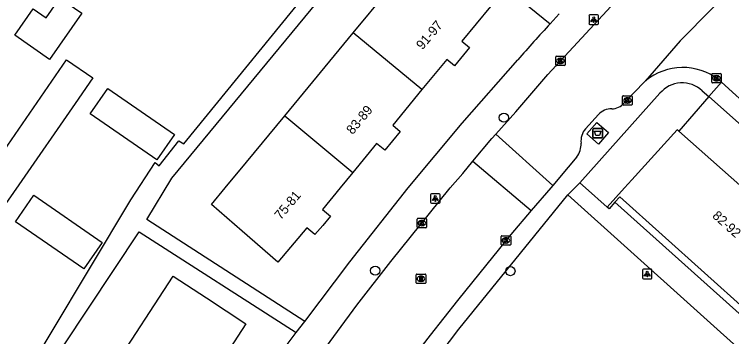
# Model space of a CAD drawing. Extents: x 160026 to 161302, y 384757 to 385701.
# Drawn here: x 160200.9 to 160276.8, y 385484.3 to 385518.4 of the extents above; entities that cross this region are included whole.
import ezdxf

# ---------------------------------------------------------------- set-up
doc = ezdxf.new("R2010")
doc.units = 0
for name, color, linetype in [('IMGEO_Afval_apart_plaats', 7, 'Continuous'), ('IMGEO_Boom', 7, 'Continuous'), ('IMGEO_Kolk', 7, 'Continuous'), ('IMGEO_Lichtpunt', 7, 'Continuous'), ('IMGEO_Pand', 7, 'Continuous'), ('IMGEO_Pand_nummerreeks', 7, 'Continuous'), ('IMGEO_Rijbaan_lokaal_gesloten', 7, 'Continuous'), ('IMGEO_Rijbaan_lokaal_open', 7, 'Continuous'), ('IMGEO_Rioolput', 7, 'Continuous'), ('IMGEO_Voetpad_gesloten', 7, 'Continuous'), ('IMGEO_Voetpad_open', 7, 'Continuous')]:
    doc.layers.add(name, color=color, linetype=linetype)

msp = doc.modelspace()

# ---------------------------------------------------------------- linework, layer by layer
at = {"layer": 'IMGEO_Afval_apart_plaats'}
for p, q in [((160262.147, 385505.395), (160262.147, 385506.195)), ((160262.147, 385506.195), (160262.147, 385505.395)), ((160262.247, 385506.295), (160263.037, 385506.295)), ((160263.037, 385506.295), (160262.247, 385506.295)), ((160263.137, 385506.195), (160263.137, 385505.395)), ((160263.137, 385505.395), (160263.137, 385506.195)), ((160263.037, 385505.295), (160262.247, 385505.295)), ((160262.247, 385505.295), (160263.037, 385505.295))]:
    msp.add_line(p, q, dxfattribs=at)
msp.add_lwpolyline([(160262.29, 385506.009), (160262.994, 385506.009), (160262.845, 385505.539), (160262.439, 385505.539), (160262.29, 385506.009)], dxfattribs=at)
for centre, start, end in [((160262.247, 385506.195), 90, 180), ((160262.247, 385506.195), 90, 180), ((160263.037, 385506.195), 0, 90), ((160263.037, 385506.195), 360, 90), ((160262.247, 385505.395), 180, 270), ((160262.247, 385505.395), 180, 270), ((160263.037, 385505.395), 270, 0), ((160263.037, 385505.395), 270, 0)]:
    msp.add_arc(centre, 0.1, start, end, dxfattribs=at)
at = {"layer": 'IMGEO_Boom'}
for centre in [(160252.715, 385507.448), (160239.098, 385491.254), (160253.404, 385491.208)]:
    msp.add_circle(centre, 0.489, dxfattribs=at)
at = {"layer": 'IMGEO_Kolk'}
for p, q in [((160258.2, 385513.021), (160258.2, 385513.873)), ((160258.275, 385513.947), (160259.127, 385513.947)), ((160258.688, 385513.727), (160258.713, 385513.727)), ((160259.201, 385513.873), (160259.201, 385513.021)), ((160259.127, 385512.947), (160258.275, 385512.947)), ((160258.711, 385513.167), (160258.686, 385513.167)), ((160274.798, 385512.117), (160275.65, 385512.117)), ((160274.723, 385511.191), (160274.723, 385512.043)), ((160275.234, 385511.337), (160275.209, 385511.337)), ((160275.211, 385511.897), (160275.236, 385511.897)), ((160275.724, 385512.043), (160275.724, 385511.191)), ((160275.65, 385511.117), (160274.798, 385511.117)), ((160265.285, 385508.841), (160265.285, 385509.693)), ((160265.36, 385509.767), (160266.212, 385509.767)), ((160265.773, 385509.547), (160265.798, 385509.547)), ((160266.286, 385509.693), (160266.286, 385508.841)), ((160266.212, 385508.767), (160265.36, 385508.767)), ((160265.796, 385508.987), (160265.771, 385508.987)), ((160243.536, 385495.866), (160243.536, 385496.718)), ((160243.611, 385496.792), (160244.463, 385496.792)), ((160244.024, 385496.572), (160244.049, 385496.572)), ((160244.537, 385496.718), (160244.537, 385495.866)), ((160244.463, 385495.792), (160243.611, 385495.792)), ((160244.047, 385496.012), (160244.022, 385496.012)), ((160252.434, 385494.024), (160252.434, 385494.876)), ((160252.509, 385494.95), (160253.361, 385494.95)), ((160252.922, 385494.73), (160252.947, 385494.73)), ((160253.435, 385494.876), (160253.435, 385494.024)), ((160253.361, 385493.95), (160252.509, 385493.95)), ((160252.945, 385494.17), (160252.92, 385494.17))]:
    msp.add_line(p, q, dxfattribs=at)
for points in [[(160258.2, 385513.021), (160258.2, 385513.873)], [(160258.275, 385513.947), (160259.127, 385513.947)], [(160258.521, 385513.647), (160258.644, 385513.647), (160258.644, 385513.496), (160258.774, 385513.647), (160258.938, 385513.647), (160258.792, 385513.496), (160258.945, 385513.247), (160258.793, 385513.247), (160258.708, 385513.411), (160258.644, 385513.344), (160258.644, 385513.247), (160258.521, 385513.247), (160258.521, 385513.647)], [(160259.201, 385513.873), (160259.201, 385513.021)], [(160259.127, 385512.947), (160258.275, 385512.947)], [(160274.798, 385512.117), (160275.65, 385512.117)], [(160274.723, 385511.191), (160274.723, 385512.043)], [(160275.044, 385511.817), (160275.167, 385511.817), (160275.167, 385511.666), (160275.297, 385511.817), (160275.461, 385511.817), (160275.315, 385511.666), (160275.468, 385511.417), (160275.316, 385511.417), (160275.231, 385511.581), (160275.167, 385511.514), (160275.167, 385511.417), (160275.044, 385511.417), (160275.044, 385511.817)], [(160275.724, 385512.043), (160275.724, 385511.191)], [(160275.65, 385511.117), (160274.798, 385511.117)], [(160265.285, 385508.841), (160265.285, 385509.693)], [(160265.36, 385509.767), (160266.212, 385509.767)], [(160265.606, 385509.467), (160265.729, 385509.467), (160265.729, 385509.316), (160265.859, 385509.467), (160266.023, 385509.467), (160265.877, 385509.316), (160266.03, 385509.067), (160265.878, 385509.067), (160265.793, 385509.231), (160265.729, 385509.164), (160265.729, 385509.067), (160265.606, 385509.067), (160265.606, 385509.467)], [(160266.286, 385509.693), (160266.286, 385508.841)], [(160266.212, 385508.767), (160265.36, 385508.767)], [(160243.536, 385495.866), (160243.536, 385496.718)], [(160243.611, 385496.792), (160244.463, 385496.792)], [(160243.857, 385496.492), (160243.98, 385496.492), (160243.98, 385496.341), (160244.11, 385496.492), (160244.274, 385496.492), (160244.128, 385496.341), (160244.281, 385496.092), (160244.129, 385496.092), (160244.044, 385496.256), (160243.98, 385496.189), (160243.98, 385496.092), (160243.857, 385496.092), (160243.857, 385496.492)], [(160244.537, 385496.718), (160244.537, 385495.866)], [(160244.463, 385495.792), (160243.611, 385495.792)], [(160252.434, 385494.024), (160252.434, 385494.876)], [(160252.509, 385494.95), (160253.361, 385494.95)], [(160252.755, 385494.65), (160252.878, 385494.65), (160252.878, 385494.499), (160253.008, 385494.65), (160253.172, 385494.65), (160253.026, 385494.499), (160253.179, 385494.25), (160253.027, 385494.25), (160252.942, 385494.414), (160252.878, 385494.347), (160252.878, 385494.25), (160252.755, 385494.25), (160252.755, 385494.65)], [(160253.435, 385494.876), (160253.435, 385494.024)], [(160253.361, 385493.95), (160252.509, 385493.95)]]:
    msp.add_lwpolyline(points, dxfattribs=at)
for centre, start, end in [((160258.277, 385513.871), 91.55205, 178.44795), ((160258.277, 385513.871), 91.55205, 178.44795), ((160259.125, 385513.871), 1.55205, 88.44795), ((160259.125, 385513.871), 1.55205, 88.44795), ((160258.277, 385513.023), 181.55205, 268.44795), ((160258.277, 385513.023), 181.55205, 268.44795), ((160259.125, 385513.023), 271.55205, 358.44795), ((160259.125, 385513.023), 271.55205, 358.44795), ((160274.8, 385512.041), 91.55205, 178.44795), ((160274.8, 385512.041), 91.55205, 178.44795), ((160275.648, 385512.041), 1.55205, 88.44795), ((160275.648, 385512.041), 1.55205, 88.44795), ((160274.8, 385511.193), 181.55205, 268.44795), ((160274.8, 385511.193), 181.55205, 268.44795), ((160275.648, 385511.193), 271.55205, 358.44795), ((160275.648, 385511.193), 271.55205, 358.44795), ((160265.362, 385509.691), 91.55205, 178.44795), ((160265.362, 385509.691), 91.55205, 178.44795), ((160266.21, 385509.691), 1.55205, 88.44795), ((160266.21, 385509.691), 1.55205, 88.44795), ((160265.362, 385508.843), 181.55205, 268.44795), ((160265.362, 385508.843), 181.55205, 268.44795), ((160266.21, 385508.843), 271.55205, 358.44795), ((160266.21, 385508.843), 271.55205, 358.44795), ((160243.613, 385496.716), 91.55205, 178.44795), ((160243.613, 385496.716), 91.55205, 178.44795), ((160244.461, 385496.716), 1.55205, 88.44795), ((160244.461, 385496.716), 1.55205, 88.44795), ((160243.613, 385495.868), 181.55205, 268.44795), ((160243.613, 385495.868), 181.55205, 268.44795), ((160244.461, 385495.868), 271.55205, 358.44795), ((160244.461, 385495.868), 271.55205, 358.44795), ((160252.511, 385494.874), 91.55205, 178.44795), ((160252.511, 385494.874), 91.55205, 178.44795), ((160253.359, 385494.874), 1.55205, 88.44795), ((160253.359, 385494.874), 1.55205, 88.44795), ((160252.511, 385494.026), 181.55205, 268.44795), ((160252.511, 385494.026), 181.55205, 268.44795), ((160253.359, 385494.026), 271.55205, 358.44795), ((160253.359, 385494.026), 271.55205, 358.44795)]:
    msp.add_arc(centre, 0.0765, start, end, dxfattribs=at)
for centre, major_axis, ratio, start_param, end_param in [((160258.687, 385513.447), (-0.387, 0.002), 0.722429, 4.712389, 7.853982), ((160258.712, 385513.447), (-0.39, 0.002), 0.717154, 1.570796, 4.712389), ((160275.21, 385511.617), (-0.387, 0.002), 0.722429, 4.712389, 7.853982), ((160275.235, 385511.617), (-0.39, 0.002), 0.717154, 1.570796, 4.712389), ((160265.772, 385509.267), (-0.387, 0.002), 0.722429, 4.712389, 7.853982), ((160265.797, 385509.267), (-0.39, 0.002), 0.717154, 1.570796, 4.712389), ((160244.023, 385496.292), (-0.387, 0.002), 0.722429, 4.712389, 7.853982), ((160244.048, 385496.292), (-0.39, 0.002), 0.717154, 1.570796, 4.712389), ((160252.921, 385494.45), (-0.387, 0.002), 0.722429, 4.712389, 7.853982), ((160252.946, 385494.45), (-0.39, 0.002), 0.717154, 1.570796, 4.712389)]:
    msp.add_ellipse(centre, major_axis=major_axis, ratio=ratio, start_param=start_param, end_param=end_param, dxfattribs=at)
at = {"layer": 'IMGEO_Lichtpunt'}
for p, q in [((160261.726, 385518.221), (160261.726, 385517.414)), ((160261.726, 385518.221), (160261.726, 385517.414)), ((160262.628, 385518.316), (160261.82, 385518.316)), ((160262.628, 385518.316), (160261.82, 385518.316)), ((160262.722, 385517.414), (160262.722, 385518.221)), ((160262.722, 385517.414), (160262.722, 385518.221)), ((160261.82, 385517.32), (160262.628, 385517.32)), ((160261.82, 385517.32), (160262.628, 385517.32)), ((160244.959, 385499.293), (160244.959, 385498.486)), ((160244.959, 385499.293), (160244.959, 385498.486)), ((160245.861, 385499.388), (160245.053, 385499.388)), ((160245.861, 385499.388), (160245.053, 385499.388)), ((160245.955, 385498.486), (160245.955, 385499.293)), ((160245.955, 385498.486), (160245.955, 385499.293)), ((160245.053, 385498.392), (160245.861, 385498.392)), ((160245.053, 385498.392), (160245.861, 385498.392)), ((160267.393, 385491.302), (160267.393, 385490.495)), ((160267.393, 385491.302), (160267.393, 385490.495)), ((160268.295, 385491.397), (160267.487, 385491.397)), ((160268.295, 385491.397), (160267.487, 385491.397)), ((160268.389, 385490.495), (160268.389, 385491.302)), ((160268.389, 385490.495), (160268.389, 385491.302)), ((160267.487, 385490.401), (160268.295, 385490.401)), ((160267.487, 385490.401), (160268.295, 385490.401))]:
    msp.add_line(p, q, dxfattribs=at)
for points in [[(160262.1, 385517.885), (160262.139, 385517.857), (160261.951, 385517.595), (160261.913, 385517.622), (160262.1, 385517.885)], [(160262.202, 385517.837), (160262.249, 385517.837), (160262.249, 385517.515), (160262.202, 385517.515), (160262.202, 385517.837)], [(160262.312, 385517.857), (160262.35, 385517.884), (160262.537, 385517.622), (160262.498, 385517.594), (160262.312, 385517.857)], [(160245.333, 385498.957), (160245.372, 385498.929), (160245.184, 385498.667), (160245.146, 385498.694), (160245.333, 385498.957)], [(160245.435, 385498.909), (160245.482, 385498.909), (160245.482, 385498.587), (160245.435, 385498.587), (160245.435, 385498.909)], [(160245.545, 385498.929), (160245.583, 385498.956), (160245.77, 385498.694), (160245.731, 385498.666), (160245.545, 385498.929)], [(160267.767, 385490.966), (160267.806, 385490.938), (160267.618, 385490.676), (160267.58, 385490.703), (160267.767, 385490.966)], [(160267.869, 385490.918), (160267.916, 385490.918), (160267.916, 385490.596), (160267.869, 385490.596), (160267.869, 385490.918)], [(160267.979, 385490.938), (160268.017, 385490.965), (160268.204, 385490.703), (160268.165, 385490.675), (160267.979, 385490.938)]]:
    msp.add_lwpolyline(points, dxfattribs=at)
for centre in [(160262.225, 385518.019), (160245.458, 385499.091), (160267.892, 385491.1)]:
    msp.add_circle(centre, 0.0994, dxfattribs=at)
for centre, start, end in [((160261.82, 385518.221), 90, 180), ((160261.82, 385518.221), 90, 180), ((160262.628, 385518.221), 0, 90), ((160262.628, 385518.221), 0, 90), ((160261.82, 385517.414), 180, 270), ((160261.82, 385517.414), 180, 270), ((160262.628, 385517.414), 270, 0), ((160262.628, 385517.414), 270, 360), ((160245.053, 385499.293), 90, 180), ((160245.053, 385499.293), 90, 180), ((160245.861, 385499.293), 0, 90), ((160245.861, 385499.293), 0, 90), ((160245.053, 385498.486), 180, 270), ((160245.053, 385498.486), 180, 270), ((160245.861, 385498.486), 270, 0), ((160245.861, 385498.486), 270, 360), ((160267.487, 385491.302), 90, 180), ((160267.487, 385491.302), 90, 180), ((160268.295, 385491.302), 0, 90), ((160268.295, 385491.302), 0, 90), ((160267.487, 385490.495), 180, 270), ((160267.487, 385490.495), 180, 270), ((160268.295, 385490.495), 270, 0), ((160268.295, 385490.495), 270, 360)]:
    msp.add_arc(centre, 0.0946, start, end, dxfattribs=at)
at = {"layer": 'IMGEO_Pand'}
for points in [[(160236.778, 385516.417), (160244.038, 385525.21), (160247.45, 385522.393), (160251.306, 385519.21), (160248.281, 385515.546), (160249.087, 385514.881), (160247.478, 385512.933), (160246.671, 385513.6), (160244.044, 385510.418)], [(160204.266, 385518.004), (160205.731, 385520.111), (160208.043, 385518.504), (160204.631, 385513.595), (160200.941, 385516.16), (160202.888, 385518.962), (160204.266, 385518.004)], [(160229.519, 385507.623), (160236.778, 385516.417)], [(160244.044, 385510.418), (160236.778, 385516.417)], [(160209.196, 385511.642), (160207.334, 385508.952), (160201.375, 385500.347), (160199.435, 385497.545), (160196.676, 385499.456), (160206.437, 385513.553), (160209.196, 385511.642)], [(160210.798, 385510.533), (160217.84, 385505.657), (160215.977, 385502.967), (160208.935, 385507.843), (160210.798, 385510.533)], [(160244.044, 385510.418), (160240.945, 385506.664), (160241.753, 385505.996), (160240.101, 385503.995), (160239.242, 385504.704), (160236.746, 385501.657)], [(160236.746, 385501.657), (160235.388, 385500), (160233.524, 385497.725), (160234.363, 385497.013), (160233.538, 385496.04), (160232.71, 385495.064), (160231.871, 385495.776), (160228.797, 385492.153), (160225.021, 385495.43), (160221.776, 385498.245), (160223.225, 385500), (160225.487, 385502.74), (160229.519, 385507.623)], [(160229.519, 385507.623), (160236.746, 385501.657)], [(160271.242, 385506.001), (160271.053, 385506.168), (160266.253, 385500.86), (160265.473, 385500), (160263.639, 385497.979)], [(160278.101, 385499.927), (160278.019, 385500), (160271.242, 385506.001)], [(160210.186, 385494.245), (160208.246, 385491.444), (160201.036, 385496.436), (160202.976, 385499.238), (160210.186, 385494.245)], [(160264.474, 385498.493), (160263.845, 385497.794), (160263.639, 385497.979)], [(160264.474, 385498.493), (160264.992, 385499.068), (160278.421, 385486.989), (160277.935, 385486.449)], [(160211.338, 385480.879), (160217.716, 385490.66), (160221.229, 385488.37), (160225.417, 385485.639), (160222.862, 385481.721), (160223.802, 385481.107), (160222.422, 385478.99), (160221.46, 385479.617), (160219.002, 385475.848)]]:
    msp.add_lwpolyline(points, dxfattribs=at)
at = {"layer": 'IMGEO_Rijbaan_lokaal_gesloten'}
for points in [[(160251.855, 385505.703), (160253.982, 385508.078), (160257.374, 385512.002), (160260.496, 385515.395), (160265.394, 385520.689), (160268.358, 385523.682), (160271.879, 385527.296), (160275.83, 385531.18), (160279.303, 385534.434), (160285.809, 385540.411), (160288.7, 385542.916), (160291.885, 385545.659), (160300.344, 385552.499)], [(160280.673, 385524.661), (160278.148, 385522.454), (160271.374, 385515.581), (160267.693, 385511.326)], [(160267.693, 385511.326), (160267.352, 385510.975), (160266.78, 385510.387), (160265.437, 385508.997)], [(160262.718, 385507.771), (160261.36, 385506.261)], [(160260.438, 385503.282), (160259.512, 385502.208), (160257.909, 385500.281)], [(160213.889, 385452.911), (160218.042, 385459.796), (160220.662, 385464.164), (160224.069, 385469.234), (160227.148, 385473.834), (160229.85, 385477.702), (160233.05, 385482.043), (160237.154, 385487.587), (160240.762, 385492.238), (160247.036, 385500), (160248.366, 385501.543), (160249.437, 385502.831)], [(160255.619, 385497.612), (160253.44, 385495.078), (160250.916, 385491.949), (160247.794, 385488.099), (160244.901, 385484.43), (160242.277, 385480.991), (160239.425, 385477.191), (160235.977, 385472.44), (160232.212, 385466.918), (160229.113, 385462.275)]]:
    msp.add_lwpolyline(points, dxfattribs=at)
for centre, radius, start, end in [((160264.084, 385506.519), 1.852, 88.40687, 137.49162), ((160264.035, 385510.246), 1.878, 273.05937, 318.29701), ((160262.762, 385504.997), 1.887, 137.962, 187.61461), ((160258.459, 385504.696), 2.433, 324.44492, 1.19029)]:
    msp.add_arc(centre, radius, start, end, dxfattribs=at)
at = {"layer": 'IMGEO_Rijbaan_lokaal_open'}
for points in [[(160275.738, 385511.192), (160275.452, 385511.45)], [(160275.738, 385511.192), (160282.611, 385505.002)], [(160274.426, 385509.67), (160271.242, 385506.001)], [(160281.366, 385503.525), (160274.426, 385509.67)], [(160249.437, 385502.831), (160251.428, 385505.226), (160251.855, 385505.703)], [(160251.855, 385505.703), (160257.909, 385500.281)], [(160249.437, 385502.831), (160255.619, 385497.612)], [(160257.909, 385500.281), (160257.671, 385500), (160255.619, 385497.612)]]:
    msp.add_lwpolyline(points, dxfattribs=at)
msp.add_arc((160271.65, 385506.539), 6.211, 52.25208, 129.5791, dxfattribs=at)
at = {"layer": 'IMGEO_Rioolput'}
for p, q in [((160243.442, 385489.971), (160243.442, 385490.823)), ((160243.517, 385490.897), (160244.369, 385490.897)), ((160244.443, 385490.823), (160244.443, 385489.971)), ((160243.953, 385490.117), (160243.928, 385490.117)), ((160243.93, 385490.677), (160243.955, 385490.677)), ((160244.369, 385489.897), (160243.517, 385489.897))]:
    msp.add_line(p, q, dxfattribs=at)
for points in [[(160243.442, 385489.971), (160243.442, 385490.823)], [(160243.517, 385490.897), (160244.369, 385490.897)], [(160244.443, 385490.823), (160244.443, 385489.971)], [(160244.031, 385490.595), (160243.779, 385490.597), (160243.779, 385490.197)], [(160243.779, 385490.197), (160243.903, 385490.197), (160243.903, 385490.359), (160243.914, 385490.359)], [(160243.957, 385490.516), (160243.903, 385490.516), (160243.903, 385490.435)], [(160243.903, 385490.435), (160243.955, 385490.435)], [(160243.961, 385490.33), (160244.032, 385490.197), (160244.172, 385490.197), (160244.107, 385490.323)], [(160244.369, 385489.897), (160243.517, 385489.897)]]:
    msp.add_lwpolyline(points, dxfattribs=at)
for centre, radius, start, end in [((160243.519, 385490.821), 0.0765, 91.55205, 178.44795), ((160243.519, 385490.821), 0.0765, 91.55205, 178.44795), ((160244.367, 385490.821), 0.0765, 1.55205, 88.44795), ((160244.367, 385490.821), 0.0765, 1.55205, 88.44795), ((160243.913, 385490.306), 0.0533, 26.02933, 88.69889), ((160243.939, 385490.624), 0.19, 274.7715, 282.96867), ((160243.963, 385490.42), 0.0964, 77.00612, 93.18647), ((160243.977, 385490.477), 0.0378, 276.66336, 79.67722), ((160244.03, 385490.485), 0.109, 350.36119, 89.41601), ((160244.028, 385490.485), 0.112, 277.58423, 350.98172), ((160244.012, 385490.27), 0.108, 29.51342, 73.79051), ((160243.519, 385489.973), 0.0765, 181.55205, 268.44795), ((160243.519, 385489.973), 0.0765, 181.55205, 268.44795), ((160244.367, 385489.973), 0.0765, 271.55205, 358.44795), ((160244.367, 385489.973), 0.0765, 271.55205, 358.44795)]:
    msp.add_arc(centre, radius, start, end, dxfattribs=at)
for centre, major_axis, ratio, start_param, end_param in [((160243.929, 385490.397), (-0.387, 0.002), 0.722429, 4.712389, 7.853982), ((160243.954, 385490.397), (-0.39, 0.002), 0.717154, 1.570796, 4.712389)]:
    msp.add_ellipse(centre, major_axis=major_axis, ratio=ratio, start_param=start_param, end_param=end_param, dxfattribs=at)
at = {"layer": 'IMGEO_Voetpad_gesloten'}
msp.add_lwpolyline([(160263.797, 385505.875), (160262.746, 385504.642), (160261.487, 385505.715), (160262.538, 385506.948), (160263.797, 385505.875)], dxfattribs=at)
at = {"layer": 'IMGEO_Voetpad_open'}
for points in [[(160231.634, 385485.876), (160214.909, 385496.65), (160217.565, 385501.027), (160241.709, 385530.294), (160257.612, 385517.389)], [(160191.188, 385464.185), (160200.423, 385477.359), (160213.246, 385498.748), (160215.8, 385502.686), (160216.228, 385502.359), (160218.318, 385504.995), (160218.845, 385504.672), (160233.689, 385522.91)], [(160257.612, 385517.389), (160258.571, 385518.44)], [(160231.634, 385485.876), (160236.399, 385492.201), (160242.58, 385500), (160248.306, 385506.859), (160254.197, 385513.573)], [(160274.426, 385509.67), (160275.738, 385511.192)], [(160260.743, 385500.538), (160269.236, 385510.037)], [(160273.695, 385510.298), (160274.426, 385509.67)], [(160260.743, 385500.538), (160259.478, 385499.269)], [(160263.639, 385497.979), (160261.352, 385500), (160260.743, 385500.538)], [(160239.052, 385473.082), (160241.913, 385477.091), (160247.946, 385485.052), (160259.478, 385499.269)], [(160259.478, 385499.269), (160279.121, 385481.597)], [(160277.935, 385486.449), (160264.474, 385498.493)], [(160192.707, 385463.153), (160214.103, 385495.368), (160230.744, 385484.695)], [(160230.744, 385484.695), (160231.634, 385485.876)], [(160210.759, 385454.57), (160216.645, 385464.267), (160220.806, 385470.55), (160229.051, 385482.447), (160230.744, 385484.695)]]:
    msp.add_lwpolyline(points, dxfattribs=at)
for centre, radius, start, end in [((160526.562, 385273.265), 363.223, 137.77023, 138.57802), ((160271.591, 385508.018), 3.102, 47.30044, 139.39934)]:
    msp.add_arc(centre, radius, start, end, dxfattribs=at)

# ---------------------------------------------------------------- texts
at = {"layer": 'IMGEO_Pand_nummerreeks'}
for s, rotation, p in [('91-97', 49.6001, (160244.093, 385514.57)), ('83-89', 50.17046, (160236.707, 385505.593)), ('75-81', 49.7738, (160229.097, 385496.571)), ('82-92', 318.03294, (160274.707, 385496.95))]:
    msp.add_text(s, height=1, rotation=rotation, dxfattribs=at).set_placement(p)

doc.saveas('drawing.dxf')
